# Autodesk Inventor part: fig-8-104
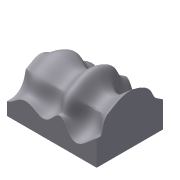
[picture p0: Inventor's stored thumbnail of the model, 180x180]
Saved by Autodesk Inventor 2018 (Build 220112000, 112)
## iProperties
Shininess: 64.0
Length Units: 11269
Angle Units: 11279
Time Units: 11290
Mass Units: 11283
Length Display Precision: 3
Angle Display Precision: 2
Compacted: True
Part Number: fig-8-104
Document SubType Name: Modeling
Created: 2002-12
Designer: deepak
Density: 1 g/cm^3
Material: Generic
Appearance: Aluminum - Flat
Density: 0.0
Volumn: 0.0
Area: 0.0
PropertySet Name: Model Information
Control State: 0
Master: False
Checked Out: False
Author: deepak
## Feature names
1. Extrusion1
## Parameters: d0 = 25 mm, d1 = 0, d2 = 0, d3 = 0
